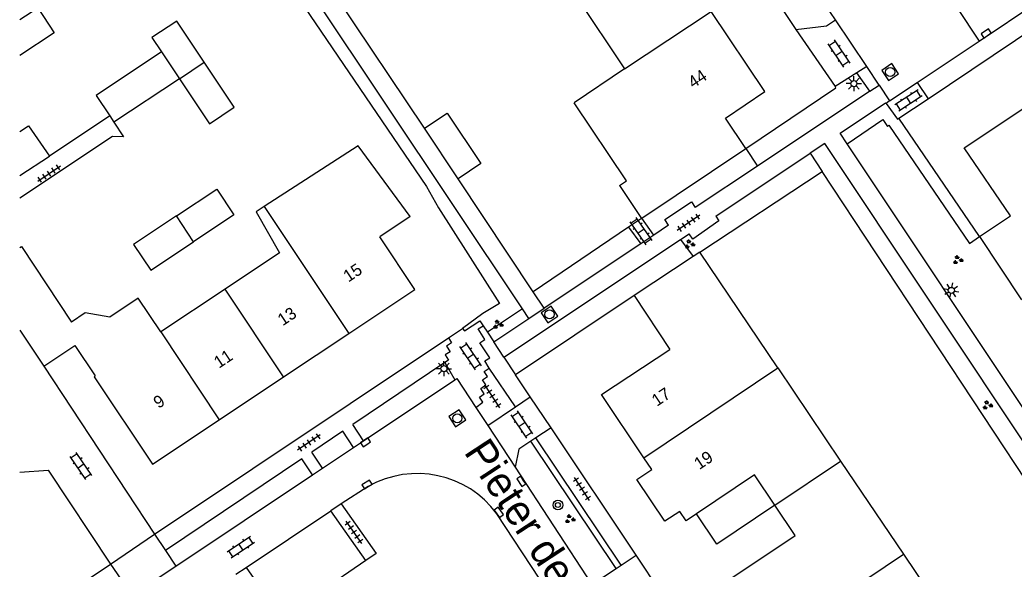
# Model space of a CAD drawing. Extents: x 137999 to 141000, y 397500 to 400501.
# Drawn here: x 138000 to 138081.8, y 399316.9 to 399362.1 of the extents above; entities that cross this region are included whole.
import ezdxf

# ---------------------------------------------------------------- set-up
doc = ezdxf.new("R2010")
doc.units = 0
for name, color, linetype in [('gg-afsc-erfafscheiding', 7, 'Continuous'), ('gg-afsc-muur', 7, 'Continuous'), ('gg-anno-huisnummerreeks BGT', 7, 'Continuous'), ('gg-anno-openbare ruimte label', 7, 'Continuous'), ('gg-bbg-bijgebouw', 7, 'Continuous'), ('gg-bbg-gedigitaliseerde bebouwing', 7, 'Continuous'), ('gg-bbg-gedigitaliseerde bijgebouw', 7, 'Continuous'), ('gg-bbg-hoofdgebouw', 7, 'Continuous'), ('gg-bbg-luifel en loopbrug', 7, 'Continuous'), ('gg-bbg-tussenscheiding', 7, 'Continuous'), ('gg-knt-verharding', 7, 'Continuous'), ('gg-knt-verharding nz', 7, 'Continuous'), ('gt-grn-groengrens', 7, 'Continuous'), ('gt-grn-vlakafsluiter', 7, 'Continuous'), ('gt-grn-weggrens', 7, 'Continuous'), ('gt-symb-boom', 7, 'Continuous'), ('gt-symb-groenvak', 7, 'Continuous'), ('gt-symb-klinker verharding', 7, 'Continuous'), ('gt-symb-kolk', 7, 'Continuous'), ('gt-symb-lichtmast', 7, 'Continuous'), ('gt-symb-rioolschacht', 7, 'Continuous'), ('gt-symb-tegel verharding', 7, 'Continuous')]:
    doc.layers.add(name, color=color, linetype=linetype)

# ---------------------------------------------------------------- blocks, each defined once
blk = doc.blocks.new('gt0-LMAST')
at = {"layer": 'gt-symb-lichtmast'}
for p, q in [((-0.182, 0.173), (-0.447, 0.438)), ((-0.005, 0.246), (-0.005, 0.621)), ((0.172, 0.173), (0.437, 0.438)), ((-0.255, -0.004), (-0.63, -0.004)), ((-0.182, -0.181), (-0.447, -0.446)), ((-0.005, -0.254), (-0.005, -0.629)), ((0.437, -0.446), (0.172, -0.181)), ((0.245, -0.004), (0.62, -0.004))]:
    blk.add_line(p, q, dxfattribs=at)
blk.add_circle((-0.005, -0.004), 0.25, dxfattribs=at)
blk = doc.blocks.new('gt0-RS')
at = {"layer": 'gt-symb-rioolschacht'}
blk.add_lwpolyline([(-0.5, -0.5), (0.5, -0.5), (0.5, 0.5), (-0.5, 0.5)], close=True, dxfattribs=at)
blk.add_circle((0, 0), 0.375, dxfattribs=at)
blk = doc.blocks.new('gt0-KOLK')
at = {"layer": 'gt-symb-kolk'}
blk.add_lwpolyline([(0, 0), (0.375, 0), (0.375, 0.4), (-0.375, 0.4), (-0.375, 0), (0, 0)], dxfattribs=at)
blk = doc.blocks.new('gt0-KL1')
at = {"layer": 'gt-symb-klinker verharding'}
for p, q in [((-1.15, 0.3), (1.15, 0.3)), ((-1, -0.3), (-1, 0.3)), ((-0.5, 0.3), (-0.5, 0.45)), ((0, -0.3), (0, 0.3)), ((0.5, 0.3), (0.5, 0.45)), ((1, -0.3), (1, 0.3)), ((-1.15, -0.3), (1.15, -0.3)), ((-0.5, -0.45), (-0.5, -0.3)), ((0.5, -0.45), (0.5, -0.3))]:
    blk.add_line(p, q, dxfattribs=at)
blk = doc.blocks.new('gt0-GRVAK')
at = {"layer": 'gt-symb-groenvak'}
for p, q in [((-0.11, 0.189), (-0.228, 0.24)), ((-0.182, 0.153), (0.088, 0.153)), ((-0.091, 0.211), (-0.156, 0.322)), ((-0.047, 0.214), (-0.047, 0.393)), ((-0.004, 0.211), (0.061, 0.322)), ((0.015, 0.189), (0.133, 0.24)), ((0.262, -0.052), (0.197, 0.059)), ((0.305, -0.049), (0.305, 0.13)), ((0.349, -0.052), (0.414, 0.059)), ((-0.245, -0.228), (-0.363, -0.177)), ((-0.318, -0.264), (-0.047, -0.264)), ((-0.226, -0.206), (-0.291, -0.095)), ((-0.183, -0.203), (-0.183, -0.024)), ((-0.139, -0.206), (-0.074, -0.095)), ((-0.12, -0.228), (-0.002, -0.177)), ((0.243, -0.074), (0.125, -0.023)), ((0.17, -0.11), (0.441, -0.11)), ((0.368, -0.074), (0.486, -0.023))]:
    blk.add_line(p, q, dxfattribs=at)
blk = doc.blocks.new('gt0-TEG1')
at = {"layer": 'gt-symb-tegel verharding'}
for p, q in [((-1.125, 0), (1.125, 0)), ((-0.9, -0.25), (-0.9, 0.25)), ((-0.45, -0.25), (-0.45, 0.25)), ((0, -0.25), (0, 0.25)), ((0.45, -0.25), (0.45, 0.25)), ((0.9, -0.25), (0.9, 0.25))]:
    blk.add_line(p, q, dxfattribs=at)
blk = doc.blocks.new('gt0-BOOM')
at = {"layer": 'gt-symb-boom'}
for radius in [0.4, 0.2]:
    blk.add_circle((0, 0), radius, dxfattribs=at)

msp = doc.modelspace()

# ---------------------------------------------------------------- linework, layer by layer
at = {"layer": 'gg-afsc-erfafscheiding'}
for p, q in [((138033.283, 399353.227), (138025.386, 399365.039)), ((138007.392, 399354.242), (138002.426, 399350.94)), ((138078.96, 399344.31), (138072.333, 399354.052)), ((138065.019, 399351.165), (138066.003, 399349.672)), ((138098.945, 399299.729), (138066.003, 399349.672))]:
    msp.add_line(p, q, dxfattribs=at)
for points in [[(138022.744, 399363.751), (138022.952, 399363.898), (138033.451, 399348.434), (138034.453, 399346.688), (138039.454, 399338.809)], [(138007.738, 399353.722), (138008.538, 399352.52), (138007.63, 399352.535), (138000, 399347.464)]]:
    msp.add_lwpolyline(points, dxfattribs=at)
at = {"layer": 'gg-afsc-muur'}
for p, q in [((138042.244, 399339.767), (138036.056, 399349.076)), ((138051.15, 399345.8), (138050.079, 399345.075)), ((138050.079, 399345.075), (138042.244, 399339.767))]:
    msp.add_line(p, q, dxfattribs=at)
at = {"layer": 'gg-bbg-bijgebouw'}
msp.add_line((138036.056, 399349.076), (138033.283, 399353.227), dxfattribs=at)
at = {"layer": 'gg-bbg-gedigitaliseerde bebouwing'}
for p, q in [((138045.178, 399364.968), (138049.757, 399358.113)), ((138049.757, 399358.113), (138045.611, 399355.326)), ((138049.927, 399348.906), (138045.611, 399355.326)), ((138049.33, 399348.505), (138049.927, 399348.906)), ((138078.96, 399344.31), (138082.43, 399339.117)), ((138021.35, 399342.973), (138016.885, 399339.987)), ((138016.885, 399339.987), (138011.611, 399336.459)), ((138062.381, 399333.516), (138067.534, 399325.828)), ((138067.534, 399325.828), (138072.702, 399318.168)), ((138072.702, 399318.168), (138077.903, 399310.46))]:
    msp.add_line(p, q, dxfattribs=at)
for points in [[(138032.11, 399345.951), (138027.841, 399351.772), (138020.111, 399346.8)], [(138020.111, 399346.8), (138019.429, 399346.361), (138021.35, 399342.973)], [(138011.611, 399336.459), (138009.741, 399339.255), (138007.403, 399337.691), (138005.377, 399338.024), (138004.237, 399337.27)]]:
    msp.add_lwpolyline(points, dxfattribs=at)
at = {"layer": 'gg-bbg-gedigitaliseerde bijgebouw'}
for p in [(138013.124, 399357.302), (138007.392, 399354.242)]:
    msp.add_line(p, (138007.738, 399353.722), dxfattribs=at)
for points in [[(138000, 399362.168), (138001.464, 399363.143), (138002.83, 399361.091), (138000, 399359.206)], [(138015.159, 399358.656), (138012.901, 399362.047), (138010.868, 399360.693), (138011.659, 399359.504)], [(138011.659, 399359.504), (138006.275, 399355.919), (138007.392, 399354.242)], [(138013.124, 399357.302), (138015.59, 399353.602), (138017.623, 399354.956), (138015.159, 399358.656)], [(138033.283, 399353.227), (138035.151, 399354.475), (138037.924, 399350.324), (138036.056, 399349.076)], [(138012.874, 399346.01), (138016.197, 399348.223), (138017.608, 399346.105), (138014.284, 399343.892)], [(138012.874, 399346.01), (138009.356, 399343.667), (138010.766, 399341.549), (138014.284, 399343.892)]]:
    msp.add_lwpolyline(points, dxfattribs=at)
at = {"layer": 'gg-bbg-hoofdgebouw'}
for p, q in [((138051.177, 399345.818), (138059.74, 399351.57)), ((138049.33, 399348.505), (138051.15, 399345.8)), ((138032.11, 399345.951), (138029.615, 399344.285)), ((138051.15, 399345.8), (138051.177, 399345.818)), ((138055.388, 399342.668), (138050.548, 399339.454)), ((138055.939, 399343.034), (138055.388, 399342.668)), ((138062.381, 399333.516), (138055.939, 399343.034)), ((138050.548, 399339.454), (138053.469, 399335.03)), ((138000, 399336.605), (138001.96, 399333.64)), ((138021.695, 399332.765), (138027.069, 399336.343)), ((138016.394, 399329.235), (138021.695, 399332.765)), ((138051.992, 399325.133), (138051.335, 399326.115))]:
    msp.add_line(p, q, dxfattribs=at)
for points in [[(138059.74, 399351.57), (138058.07, 399354.06), (138061.3, 399356.24), (138056.888, 399362.843)], [(138078.96, 399344.31), (138081.5, 399346.01), (138077.71, 399351.62), (138082.927, 399355.11)], [(138027.069, 399336.343), (138032.501, 399339.96), (138029.615, 399344.285)], [(138000, 399343.411), (138000.12, 399343.49), (138004.237, 399337.27)], [(138001.96, 399333.64), (138004.525, 399335.345), (138006.202, 399332.841), (138006.11, 399332.78)], [(138051.335, 399326.115), (138047.85, 399331.32), (138053.469, 399335.03)], [(138006.11, 399332.78), (138010.92, 399325.59), (138016.394, 399329.235)], [(138054.292, 399321.698), (138053.07, 399320.879), (138050.77, 399324.315), (138051.992, 399325.133)], [(138062.13, 399322.21), (138060.46, 399324.7), (138055.685, 399321.491)], [(138058.784, 399315.009), (138058.16, 399315.94), (138063.8, 399319.72), (138062.13, 399322.21)], [(138055.685, 399321.491), (138054.82, 399320.91), (138054.292, 399321.698)]]:
    msp.add_lwpolyline(points, dxfattribs=at)
at = {"layer": 'gg-bbg-luifel en loopbrug'}
msp.add_line((138000, 399349.328), (138002.426, 399350.94), dxfattribs=at)
for points in [[(138000, 399352.947), (138000.698, 399353.431), (138002.426, 399350.94)], [(138062.13, 399322.21), (138057.352, 399319.005), (138055.685, 399321.491)]]:
    msp.add_lwpolyline(points, dxfattribs=at)
at = {"layer": 'gg-bbg-tussenscheiding'}
for p, q in [((138049.757, 399358.113), (138056.888, 399362.843)), ((138011.659, 399359.504), (138013.124, 399357.302)), ((138013.124, 399357.302), (138015.159, 399358.656)), ((138020.111, 399346.8), (138027.069, 399336.343)), ((138014.284, 399343.892), (138012.874, 399346.01)), ((138021.695, 399332.765), (138016.885, 399339.987)), ((138011.611, 399336.459), (138016.394, 399329.235)), ((138051.335, 399326.115), (138062.381, 399333.516)), ((138062.13, 399322.21), (138067.534, 399325.828)), ((138061.64, 399310.75), (138072.702, 399318.168))]:
    msp.add_line(p, q, dxfattribs=at)
at = {"layer": 'gg-knt-verharding'}
for p, q in [((138078.94, 399360.401), (138131.167, 399395.345)), ((138041.358, 399338.353), (138007.308, 399389.459)), ((138074.73, 399355.659), (138098.384, 399371.52)), ((138067.12, 399362.137), (138062.864, 399368.511)), ((138069.682, 399358.298), (138067.12, 399362.137)), ((138063.848, 399361.367), (138067.081, 399356.657)), ((138073.839, 399356.988), (138078.94, 399360.401)), ((138069.682, 399358.298), (138068.882, 399357.794)), ((138070.697, 399356.778), (138069.682, 399358.298)), ((138068.882, 399357.794), (138067.081, 399356.657)), ((138069.929, 399356.266), (138068.882, 399357.794)), ((138070.697, 399356.778), (138071.57, 399355.47)), ((138071.57, 399355.47), (138073.839, 399356.988)), ((138073.839, 399356.988), (138074.73, 399355.659)), ((138069.929, 399356.266), (138060.706, 399350.12)), ((138072.333, 399354.052), (138074.73, 399355.659)), ((138071.57, 399355.47), (138071.277, 399355.258)), ((138084.158, 399327.79), (138068.072, 399351.944)), ((138057.258, 399345.994), (138065.019, 399351.165)), ((138060.706, 399350.12), (138055.57, 399346.697)), ((138052.154, 399344.421), (138051.177, 399345.818)), ((138050.079, 399345.075), (138051.088, 399343.711)), ((138053.381, 399345.239), (138052.154, 399344.421)), ((138039.83, 399334.38), (138054.365, 399344.066)), ((138052.154, 399344.421), (138051.088, 399343.711)), ((138054.365, 399344.066), (138055.07, 399344.536)), ((138051.088, 399343.711), (138043.144, 399338.418)), ((138050.548, 399339.454), (138040.793, 399332.939)), ((138043.144, 399338.418), (138042.244, 399339.767)), ((138041.877, 399337.573), (138041.358, 399338.353)), ((138038.99, 399335.65), (138041.877, 399337.573)), ((138035.257, 399335.983), (138036.42, 399336.76)), ((138038.124, 399336.968), (138038.476, 399336.433)), ((138011.087, 399319.824), (138035.257, 399335.983)), ((138038.476, 399336.433), (138038.99, 399335.65)), ((138039.83, 399334.38), (138040.793, 399332.939)), ((138001.96, 399333.64), (138011.087, 399319.824)), ((138034.962, 399333.942), (138027.393, 399328.843)), ((138034.962, 399333.942), (138035.795, 399332.527)), ((138040.77, 399330.297), (138038.611, 399333.477)), ((138042.001, 399331.13), (138040.793, 399332.939)), ((138028.281, 399327.513), (138035.795, 399332.527)), ((138040.77, 399330.297), (138042.001, 399331.13)), ((138043.703, 399328.582), (138042.001, 399331.13)), ((138037.508, 399330.255), (138037.789, 399329.826)), ((138038.492, 399328.754), (138040.77, 399330.297)), ((138037.789, 399329.826), (138038.492, 399328.754)), ((138028.281, 399327.513), (138027.393, 399328.843)), ((138038.492, 399328.754), (138040.742, 399325.322)), ((138043.703, 399328.582), (138042.466, 399327.756)), ((138050.716, 399318.084), (138043.703, 399328.582)), ((138026.564, 399328.284), (138024.034, 399326.58)), ((138027.449, 399326.958), (138026.564, 399328.284)), ((138042.466, 399327.756), (138042.05, 399327.478)), ((138049.472, 399317.261), (138042.466, 399327.756)), ((138024.912, 399325.265), (138027.449, 399326.958)), ((138027.449, 399326.958), (138028.281, 399327.513)), ((138024.912, 399325.265), (138024.034, 399326.58)), ((138023.205, 399326.022), (138011.986, 399318.464)), ((138024.081, 399324.71), (138023.205, 399326.022)), ((138024.081, 399324.71), (138024.912, 399325.265)), ((138040.742, 399325.322), (138047.07, 399315.671)), ((138012.822, 399317.198), (138024.081, 399324.71)), ((138028.668, 399323.738), (138026.433, 399322.305)), ((138026.433, 399322.305), (138025.584, 399321.738)), ((138028.472, 399317.651), (138025.584, 399321.738)), ((138046.834, 399309.96), (138039.246, 399321.497)), ((138011.087, 399319.824), (138011.986, 399318.464)), ((138011.986, 399318.464), (138012.822, 399317.198)), ((138049.472, 399317.261), (138050.716, 399318.084)), ((138053.887, 399313.337), (138050.716, 399318.084)), ((138000, 399312.366), (138007.462, 399317.364)), ((138007.462, 399317.364), (138008.295, 399316.109)), ((138009.184, 399314.77), (138012.822, 399317.198)), ((138017.771, 399316.524), (138018.619, 399317.09)), ((138018.619, 399317.09), (138021.542, 399312.921)), ((138028.472, 399317.651), (138021.542, 399312.921)), ((138049.055, 399316.985), (138049.472, 399317.261)), ((138047.07, 399315.671), (138049.055, 399316.985))]:
    msp.add_line(p, q, dxfattribs=at)
for points in [[(138063.848, 399361.367), (138066.375, 399361.645), (138067.12, 399362.137)], [(138068.072, 399351.944), (138067.493, 399352.813), (138071.24, 399355.31), (138071.277, 399355.258)], [(138071.277, 399355.258), (138072.21, 399353.97), (138072.333, 399354.052)], [(138099.47, 399298.934), (138100.915, 399299.904), (138066.228, 399351.971), (138065.019, 399351.165)], [(138053.381, 399345.239), (138053.07, 399345.706), (138055.251, 399347.176), (138055.57, 399346.697)], [(138057.258, 399345.994), (138057.52, 399345.601), (138055.361, 399344.098), (138055.07, 399344.536)], [(138036.42, 399336.76), (138036.58, 399336.56), (138037.86, 399337.37), (138038.124, 399336.968)], [(138038.611, 399333.477), (138038.252, 399334.077), (138038.665, 399334.324), (138037.842, 399335.573), (138038.245, 399335.852), (138037.715, 399336.716), (138038.124, 399336.968)], [(138035.257, 399335.983), (138035.529, 399335.556), (138035.108, 399335.297), (138035.395, 399334.837), (138034.992, 399334.576), (138035.261, 399334.142), (138034.962, 399333.942)], [(138037.508, 399330.255), (138038.095, 399330.672), (138037.817, 399331.096), (138038.2, 399331.368), (138037.938, 399331.81), (138038.346, 399332.099), (138038.068, 399332.51), (138038.468, 399332.806), (138038.207, 399333.208), (138038.611, 399333.477)], [(138035.795, 399332.527), (138035.95, 399332.63), (138037.508, 399330.255)], [(138042.05, 399327.478), (138041.065, 399326.82), (138040.742, 399325.322)], [(138000, 399324.922), (138002.34, 399325.08), (138007.462, 399317.364)], [(138026.433, 399322.305), (138029.32, 399318.23), (138028.472, 399317.651)]]:
    msp.add_lwpolyline(points, dxfattribs=at)
msp.add_arc((138032.7, 399316.683), 8.126, 36.33164, 119.74531, dxfattribs=at)
at = {"layer": 'gg-knt-verharding nz'}
msp.add_line((138018.619, 399317.09), (138025.584, 399321.738), dxfattribs=at)
at = {"layer": 'gt-grn-groengrens'}
for p, q in [((138059.74, 399351.57), (138060.706, 399350.12)), ((138055.939, 399343.034), (138066.003, 399349.672)), ((138054.365, 399344.066), (138055.388, 399342.668)), ((138041.358, 399338.353), (138038.476, 399336.433)), ((138049.055, 399316.985), (138042.05, 399327.478))]:
    msp.add_line(p, q, dxfattribs=at)
for points in [[(138059.74, 399351.57), (138067.154, 399356.55), (138067.081, 399356.657)], [(138068.072, 399351.944), (138071, 399353.937), (138071.4, 399353.384), (138071.506, 399353.49), (138078.133, 399343.747), (138078.96, 399344.31)]]:
    msp.add_lwpolyline(points, dxfattribs=at)
at = {"layer": 'gt-grn-vlakafsluiter'}
msp.add_lwpolyline([(138039.454, 399338.809), (138038.107, 399337.983), (138036.42, 399336.76)], dxfattribs=at)
at = {"layer": 'gt-grn-weggrens'}
for p, q in [((138060.261, 399366.748), (138063.848, 399361.367)), ((138077.087, 399363.172), (138078.94, 399360.401)), ((138069.929, 399356.266), (138070.697, 399356.778)), ((138041.877, 399337.573), (138043.144, 399338.418)), ((138039.83, 399334.38), (138038.99, 399335.65)), ((138007.462, 399317.364), (138011.087, 399319.824))]:
    msp.add_line(p, q, dxfattribs=at)

# ---------------------------------------------------------------- block references
at = {"layer": 'gt-symb-boom'}
msp.add_blockref('gt0-BOOM', (138044.271, 399322.218), dxfattribs=at)
at = {"layer": 'gt-symb-groenvak'}
for p in [(138055.095, 399343.684), (138077.173, 399342.39), (138039.325, 399337.072), (138079.61, 399330.432), (138045.252, 399321.06)]:
    msp.add_blockref('gt0-GRVAK', p, dxfattribs=at)
at = {"layer": 'gt-symb-klinker verharding'}
for p, rotation in [((138067.415, 399359.381), 123.99203971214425), ((138073.115, 399355.524), -146.9617153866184), ((138051.125, 399344.756), 124.97793222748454), ((138037.096, 399334.47), 123.99203971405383), ((138041.33, 399328.85), 123.99203971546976), ((138005.036, 399325.432), 123.99203971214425), ((138018.18, 399318.769), 33.992039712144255)]:
    msp.add_blockref('gt0-KL1', p, dxfattribs=dict(at, rotation=rotation))
at = {"layer": 'gt-symb-kolk'}
for p, rotation in [((138079.621, 399360.863), 33.78542795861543), ((138028.55, 399327.212), 33.705956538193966), ((138041.423, 399324.276), 123.24493724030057), ((138028.668, 399323.738), 31.558864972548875), ((138039.246, 399321.497), -53.833795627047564)]:
    msp.add_blockref('gt0-KOLK', p, dxfattribs=dict(at, rotation=rotation))
at = {"layer": 'gt-symb-lichtmast'}
for p in [(138068.628, 399356.902), (138034.895, 399333.442)]:
    msp.add_blockref('gt0-LMAST', p, dxfattribs=at)
at = {"layer": 'gt-symb-lichtmast', "rotation": -56.34172813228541}
msp.add_blockref('gt0-LMAST', (138076.648, 399339.879), dxfattribs=at)
at = {"layer": 'gt-symb-rioolschacht'}
for p, rotation in [((138071.611, 399357.854), -56.29404346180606), ((138043.58, 399337.904), 33.864943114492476), ((138035.996, 399329.359), 33.705956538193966)]:
    msp.add_blockref('gt0-RS', p, dxfattribs=dict(at, rotation=rotation))
at = {"layer": 'gt-symb-tegel verharding'}
for p, rotation in [((138002.401, 399349.501), 33.78542795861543), ((138055.014, 399345.453), -146.0079602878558), ((138038.873, 399331.168), 123.00706175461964), ((138023.782, 399327.365), -146.0079602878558), ((138046.251, 399323.544), 123.00706175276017), ((138027.496, 399319.982), 125.43780146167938)]:
    msp.add_blockref('gt0-TEG1', p, dxfattribs=dict(at, rotation=rotation))

# ---------------------------------------------------------------- texts
at = {"layer": 'gg-anno-huisnummerreeks BGT'}
for s, rotation, p in [('44', 33.8, (138055.4, 399356.472)), ('15', 33.7, (138027.033, 399340.523)), ('13', 33.7, (138021.63, 399336.926)), ('11', 33.7, (138016.381, 399333.431)), ('17', 33.8, (138052.415, 399330.295)), ('9', 33.7, (138011.413, 399330.122)), ('19', 33.8, (138055.902, 399325.086))]:
    msp.add_text(s, height=1, rotation=rotation, dxfattribs=at).set_placement(p)
at = {"layer": 'gg-anno-openbare ruimte label'}
msp.add_text('Pieter de Hooghlaan', height=2.5, rotation=303.3, dxfattribs=at).set_placement((138036.482, 399326.581))

doc.saveas('drawing.dxf')
